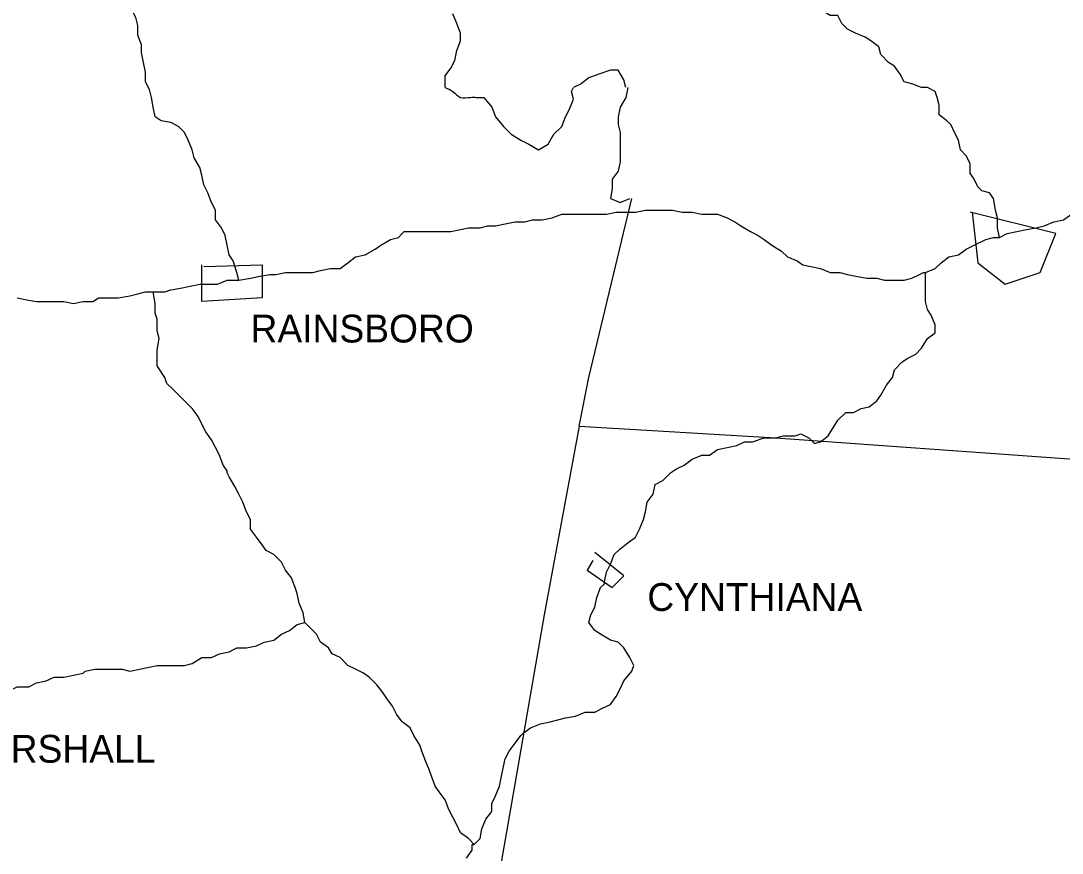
# Model space of a CAD drawing. Extents: x 0 to 34, y 0 to 22.
# Drawn here: x 4.42 to 5.15, y 18.276 to 18.859 of the extents above; entities that cross this region are included whole.
import ezdxf

# ---------------------------------------------------------------- set-up
doc = ezdxf.new("R2010")
doc.units = 0
doc.layers.add('Default', color=7, linetype='Continuous')

msp = doc.modelspace()

# ---------------------------------------------------------------- linework, layer by layer
at = {"layer": 'Default'}
for points in [[(5.05595, 18.81246), (5.05186, 18.81246), (5.04505, 18.81519), (5.03959, 18.81655), (5.03686, 18.822), (5.03277, 18.82746), (5.02868, 18.83019), (5.02323, 18.83564), (5.02187, 18.84109), (5.01641, 18.84518), (5.01232, 18.84791), (5.00551, 18.85064), (5.00005, 18.85336), (4.99596, 18.85745), (4.99324, 18.86291), (4.98778, 18.86291), (4.98369, 18.86563), (4.98096, 18.87109), (4.97824, 18.87791), (4.97687, 18.87927), (4.97687, 18.87927)], [(4.51467, 18.79201), (4.51331, 18.79883), (4.51195, 18.80564), (4.51058, 18.8111), (4.50786, 18.81655), (4.50786, 18.82337), (4.50649, 18.83019), (4.50513, 18.837), (4.50513, 18.84246), (4.5024, 18.84927), (4.5024, 18.85609), (4.50104, 18.86154), (4.49831, 18.867), (4.49286, 18.87109)], [(4.71782, 18.81246), (4.71782, 18.82064), (4.72191, 18.8261), (4.72464, 18.83155), (4.726, 18.83837), (4.72873, 18.84518), (4.72873, 18.85064), (4.726, 18.85745), (4.72328, 18.86427)], [(4.84462, 18.81246), (4.84326, 18.81791), (4.83917, 18.82473), (4.83372, 18.82473), (4.82553, 18.822), (4.81872, 18.81928), (4.81326, 18.81519), (4.80781, 18.81246)], [(4.73964, 18.80564), (4.74509, 18.80564), (4.75055, 18.79883), (4.75327, 18.79201), (4.75873, 18.78519), (4.76418, 18.77974), (4.771, 18.77565), (4.77645, 18.77292), (4.78327, 18.76883), (4.79009, 18.77292), (4.79418, 18.77974), (4.79963, 18.78519), (4.80236, 18.79201), (4.80508, 18.79746), (4.80781, 18.80428), (4.80645, 18.80973), (4.80781, 18.81246)], [(4.84599, 18.81246), (4.84462, 18.80564), (4.84053, 18.79883), (4.83917, 18.79201), (4.83917, 18.78656), (4.84053, 18.7811), (4.84053, 18.77429), (4.84053, 18.76747), (4.84053, 18.76065), (4.83917, 18.75383), (4.83508, 18.74838), (4.83508, 18.74156), (4.83372, 18.73475), (4.84053, 18.73202), (4.84735, 18.73475)], [(5.1064, 18.70748), (5.10504, 18.71429), (5.10504, 18.72111), (5.10367, 18.72657), (5.10231, 18.73475), (5.09958, 18.73884), (5.09413, 18.7402), (5.0914, 18.74293), (5.08867, 18.74838), (5.08595, 18.75247), (5.08595, 18.75929), (5.08322, 18.76474), (5.07913, 18.76883), (5.07777, 18.77565), (5.07504, 18.7811), (5.07231, 18.78656), (5.06959, 18.78928), (5.06413, 18.79337), (5.06413, 18.80019), (5.06277, 18.80564), (5.06141, 18.80973), (5.05595, 18.81246), (5.05595, 18.81246)], [(4.5733, 18.67748), (4.57194, 18.68294), (4.56921, 18.69112), (4.56648, 18.69521), (4.56512, 18.70202), (4.56376, 18.70884), (4.56103, 18.71429), (4.55694, 18.71975), (4.55694, 18.72657), (4.55421, 18.73202), (4.55149, 18.73884), (4.54876, 18.74429), (4.5474, 18.75111), (4.54603, 18.75656), (4.54194, 18.76338), (4.54058, 18.76883), (4.53785, 18.77565), (4.53513, 18.7811), (4.53104, 18.78519), (4.52558, 18.78792), (4.51876, 18.78928), (4.51467, 18.79201), (4.51467, 18.79201)], [(5.1064, 18.70748), (5.11185, 18.7102), (5.11867, 18.71157), (5.12549, 18.71293), (5.1323, 18.71429), (5.13776, 18.71566), (5.14458, 18.71838), (5.15139, 18.71975), (5.15685, 18.72384), (5.1623, 18.7252), (5.16912, 18.72657), (5.17457, 18.73066), (5.18002, 18.73202), (5.18684, 18.73475), (5.19229, 18.73747), (5.19639, 18.73884), (5.19639, 18.73884)], [(4.8119, 18.57523), (4.81872, 18.60931), (4.84871, 18.73475)], [(4.68919, 18.71157), (4.69601, 18.71157), (4.70283, 18.71157), (4.70964, 18.71157), (4.71646, 18.71157), (4.72191, 18.71157), (4.72873, 18.71293), (4.73419, 18.71429), (4.74237, 18.71429), (4.74782, 18.71566), (4.75327, 18.71566), (4.76009, 18.71702), (4.76691, 18.71838), (4.77372, 18.71838), (4.77918, 18.71975), (4.786, 18.71975), (4.79281, 18.72111), (4.79963, 18.72384), (4.80508, 18.72384), (4.81054, 18.72384), (4.81735, 18.72384), (4.82417, 18.72384), (4.83099, 18.72384), (4.83781, 18.7252), (4.84326, 18.7252), (4.84599, 18.7252)], [(4.84599, 18.7252), (4.85144, 18.7252), (4.85826, 18.72657), (4.86507, 18.72657), (4.87053, 18.72657), (4.87734, 18.72657), (4.88416, 18.7252), (4.89098, 18.7252), (4.8978, 18.72384), (4.90325, 18.72384), (4.9087, 18.72384), (4.91552, 18.72111), (4.92097, 18.71838), (4.92506, 18.71566), (4.93188, 18.71157), (4.93734, 18.70884), (4.94143, 18.70611), (4.94688, 18.70202), (4.9537, 18.69793), (4.95779, 18.69384), (4.9646, 18.69112), (4.96869, 18.68839), (4.97415, 18.68703), (4.98096, 18.68566), (4.98778, 18.68294), (4.9946, 18.68294), (5.00005, 18.68157), (5.00687, 18.68021), (5.01369, 18.67885), (5.0205, 18.67885), (5.02596, 18.67748), (5.03141, 18.67748), (5.03959, 18.67748), (5.04505, 18.67885), (5.0505, 18.68157), (5.05323, 18.68294), (5.05459, 18.68294)], [(5.08731, 18.7252), (5.0914, 18.68975), (5.11049, 18.67476), (5.13503, 18.68294), (5.14594, 18.7102), (5.08595, 18.7252)], [(4.5733, 18.67748), (4.58148, 18.67885), (4.58694, 18.68021), (4.59512, 18.68157), (4.59921, 18.68157), (4.60602, 18.68294), (4.61284, 18.68294), (4.61966, 18.68294), (4.62511, 18.68294), (4.63057, 18.6843), (4.63738, 18.68566), (4.6442, 18.68566), (4.64965, 18.68975), (4.65511, 18.69384), (4.66192, 18.69521), (4.66874, 18.6993), (4.67283, 18.70202), (4.67965, 18.70611), (4.6851, 18.70748), (4.68783, 18.7102), (4.68919, 18.71157)], [(5.05459, 18.68294), (5.06141, 18.68566), (5.0655, 18.68975), (5.07095, 18.69384), (5.07777, 18.69521), (5.08322, 18.6993), (5.08867, 18.70202), (5.08867, 18.70202)], [(5.05459, 18.68294), (5.06141, 18.68566), (5.0655, 18.68975), (5.07095, 18.69384), (5.07777, 18.69521), (5.08322, 18.6993), (5.08867, 18.70202), (5.08867, 18.70202)], [(5.08867, 18.70202), (5.09686, 18.70611), (5.10231, 18.70748), (5.1064, 18.70748)], [(5.08867, 18.70202), (5.09686, 18.70611), (5.10231, 18.70748), (5.1064, 18.70748)], [(4.54876, 18.68703), (4.58966, 18.68839), (4.58966, 18.66521), (4.5474, 18.66248), (4.5474, 18.68839)], [(4.94961, 18.56705), (4.95506, 18.56841), (4.96324, 18.56841), (4.96733, 18.56977), (4.97278, 18.56705), (4.97687, 18.56295), (4.98096, 18.56432), (4.98642, 18.56841), (4.99051, 18.57523), (4.99324, 18.57932), (4.99869, 18.58477), (5.00414, 18.58477), (5.0096, 18.5875), (5.01505, 18.58886), (5.0205, 18.59295), (5.02323, 18.59704), (5.02732, 18.60386), (5.03141, 18.60931), (5.03277, 18.61476), (5.03823, 18.62022), (5.04232, 18.62295), (5.04777, 18.62567), (5.05186, 18.62976), (5.05595, 18.63658), (5.06141, 18.64067), (5.06141, 18.64612), (5.05868, 18.65294), (5.05595, 18.65703), (5.05459, 18.66248), (5.05459, 18.6693), (5.05459, 18.67476), (5.05459, 18.68294), (5.05459, 18.68294), (5.05459, 18.68294)], [(4.51331, 18.6693), (4.52149, 18.6693), (4.52558, 18.67067), (4.5324, 18.67203), (4.53922, 18.67339), (4.54603, 18.67476), (4.55149, 18.67476), (4.5583, 18.67476), (4.56512, 18.67748), (4.57194, 18.67748), (4.5733, 18.67748)], [(4.51331, 18.6693), (4.52149, 18.6693), (4.52558, 18.67067), (4.5324, 18.67203), (4.53922, 18.67339), (4.54603, 18.67476), (4.55149, 18.67476), (4.5583, 18.67476), (4.56512, 18.67748), (4.57194, 18.67748), (4.5733, 18.67748)], [(4.41787, 18.66521), (4.42469, 18.66385), (4.43151, 18.66248), (4.43832, 18.66248), (4.44378, 18.66248), (4.45059, 18.66248), (4.45741, 18.66112), (4.46423, 18.66248), (4.47105, 18.66248), (4.47514, 18.66521), (4.48332, 18.66521), (4.48877, 18.66521), (4.49695, 18.66657), (4.5024, 18.66794), (4.50786, 18.6693), (4.51331, 18.6693)], [(4.56512, 18.54387), (4.56239, 18.54796), (4.55967, 18.55477), (4.55694, 18.56023), (4.55421, 18.56568), (4.55012, 18.57114), (4.5474, 18.57659), (4.54467, 18.58204), (4.54058, 18.5875), (4.53649, 18.59159), (4.5324, 18.59568), (4.52695, 18.60113), (4.52286, 18.60522), (4.52149, 18.60931), (4.51604, 18.61749), (4.51604, 18.62295), (4.51604, 18.6284), (4.5174, 18.63658), (4.51604, 18.64203), (4.51604, 18.65021), (4.51467, 18.6543), (4.51467, 18.66112), (4.51331, 18.6693), (4.51331, 18.6693)], [(4.8119, 18.57523), (4.78736, 18.44297), (4.76691, 18.32572), (4.75327, 18.24664), (4.73828, 18.1662), (4.72191, 18.0803), (4.69192, 17.93305)], [(4.8119, 18.57523), (4.94961, 18.56705), (5.52088, 18.52614), (6.15214, 18.48115), (6.81204, 18.43207)], [(4.82962, 18.46615), (4.83099, 18.47297), (4.83372, 18.47842), (4.83644, 18.48524), (4.84053, 18.48933), (4.84599, 18.49342), (4.85144, 18.49751), (4.85417, 18.50296), (4.85689, 18.50978), (4.85826, 18.51524), (4.85962, 18.52205), (4.86371, 18.52751), (4.86507, 18.53432), (4.87053, 18.53705), (4.87598, 18.5425), (4.88007, 18.54523), (4.88553, 18.54796), (4.89098, 18.55205), (4.8978, 18.55477), (4.90325, 18.55477), (4.9087, 18.55886), (4.91552, 18.56023), (4.92234, 18.56159), (4.92779, 18.56432), (4.93324, 18.56432), (4.94143, 18.56705), (4.94688, 18.56705), (4.94961, 18.56705)], [(4.61966, 18.43752), (4.61829, 18.44434), (4.61557, 18.45115), (4.6142, 18.45797), (4.61284, 18.46206), (4.61011, 18.46888), (4.60602, 18.47433), (4.6033, 18.47979), (4.59784, 18.48524), (4.59239, 18.48797), (4.58966, 18.49206), (4.58557, 18.49751), (4.58148, 18.50296), (4.58148, 18.50978), (4.57876, 18.51524), (4.57603, 18.52205), (4.5733, 18.52751), (4.57057, 18.53296), (4.56648, 18.53978), (4.56512, 18.5425), (4.56512, 18.54387)], [(4.82144, 18.48115), (4.81735, 18.47433), (4.83508, 18.46206), (4.84326, 18.47024), (4.82281, 18.4866)], [(4.77236, 18.35981), (4.77781, 18.3639), (4.78463, 18.36662), (4.79145, 18.36799), (4.7969, 18.36935), (4.80236, 18.37071), (4.80917, 18.37208), (4.81599, 18.3748), (4.82281, 18.3748), (4.82826, 18.37753), (4.83372, 18.38026), (4.83781, 18.38571), (4.84053, 18.39116), (4.84326, 18.39662), (4.84871, 18.40343), (4.85008, 18.40752), (4.84735, 18.41298), (4.84326, 18.4198), (4.83917, 18.42389), (4.83372, 18.42525), (4.8269, 18.42934), (4.82281, 18.43207), (4.81872, 18.43752), (4.82008, 18.44297), (4.82281, 18.44843), (4.82417, 18.45524), (4.8269, 18.46206), (4.82962, 18.46479), (4.82962, 18.46615)], [(4.46559, 18.40343), (4.47241, 18.4048), (4.47786, 18.4048), (4.48332, 18.4048), (4.4915, 18.4048), (4.49695, 18.40343), (4.50377, 18.4048), (4.50922, 18.40616), (4.51604, 18.40752), (4.52286, 18.40752), (4.52967, 18.40752), (4.53513, 18.40752), (4.54058, 18.40889), (4.5474, 18.41298), (4.55421, 18.41298), (4.55967, 18.41571), (4.56648, 18.41707), (4.57194, 18.4198), (4.57876, 18.4198), (4.58557, 18.42116), (4.59103, 18.42389), (4.59784, 18.42525), (4.6033, 18.42934), (4.60875, 18.43207), (4.6142, 18.43616), (4.61966, 18.43752)], [(4.73828, 18.28209), (4.73419, 18.28618), (4.72873, 18.29027), (4.726, 18.29572), (4.72328, 18.30118), (4.72055, 18.30663), (4.71782, 18.31345), (4.71373, 18.3189), (4.71101, 18.32299), (4.70828, 18.32981), (4.70692, 18.3339), (4.70419, 18.34072), (4.70146, 18.34753), (4.7001, 18.35162), (4.69601, 18.35844), (4.69328, 18.3639), (4.68783, 18.36799), (4.68374, 18.37344), (4.68101, 18.37889), (4.67692, 18.38435), (4.67419, 18.38844), (4.6701, 18.39389), (4.66465, 18.39934), (4.66056, 18.40207), (4.65511, 18.4048), (4.64965, 18.40752), (4.6442, 18.41298), (4.63875, 18.41571), (4.63602, 18.4198), (4.63057, 18.42389), (4.62784, 18.42934), (4.62238, 18.43479), (4.61966, 18.43752), (4.61966, 18.43752), (4.61966, 18.43752)], [(4.34561, 18.37344), (4.35243, 18.37344), (4.35788, 18.3748), (4.36333, 18.37753), (4.36879, 18.37889), (4.37697, 18.38026), (4.38242, 18.38026), (4.38924, 18.38298), (4.39333, 18.38298), (4.40151, 18.38571), (4.40696, 18.38844), (4.41242, 18.3898), (4.41787, 18.39253), (4.42605, 18.39253), (4.43151, 18.39525), (4.43832, 18.39662), (4.44378, 18.39934), (4.45059, 18.39934), (4.45741, 18.40071), (4.46423, 18.40207), (4.46559, 18.40343)], [(4.73828, 18.28209), (4.74237, 18.28618), (4.74373, 18.293), (4.74646, 18.29981), (4.75055, 18.30527), (4.75055, 18.31072), (4.75327, 18.31618), (4.756, 18.32299), (4.75736, 18.32981), (4.75873, 18.33663), (4.76009, 18.34208), (4.76282, 18.34753), (4.76691, 18.35299), (4.771, 18.35844), (4.77236, 18.35981)], [(4.73282, 18.27255), (4.73691, 18.278), (4.73691, 18.28209), (4.73691, 18.28209), (4.73828, 18.28209)]]:
    msp.add_lwpolyline(points, dxfattribs=at)
msp.add_spline([(4.71782, 18.81246), (4.72328, 18.80973), (4.72873, 18.80564), (4.73555, 18.80564), (4.73964, 18.80564)], degree=3, dxfattribs=at)

# ---------------------------------------------------------------- texts
for s, p in [('RAINSBORO', (4.58148, 18.63385)), ('CYNTHIANA', (4.85962, 18.4457)), ('MARSHALL', (4.37424, 18.33935))]:
    msp.add_text(s, height=0.019502, dxfattribs=at).set_placement(p)

doc.saveas('drawing.dxf')
